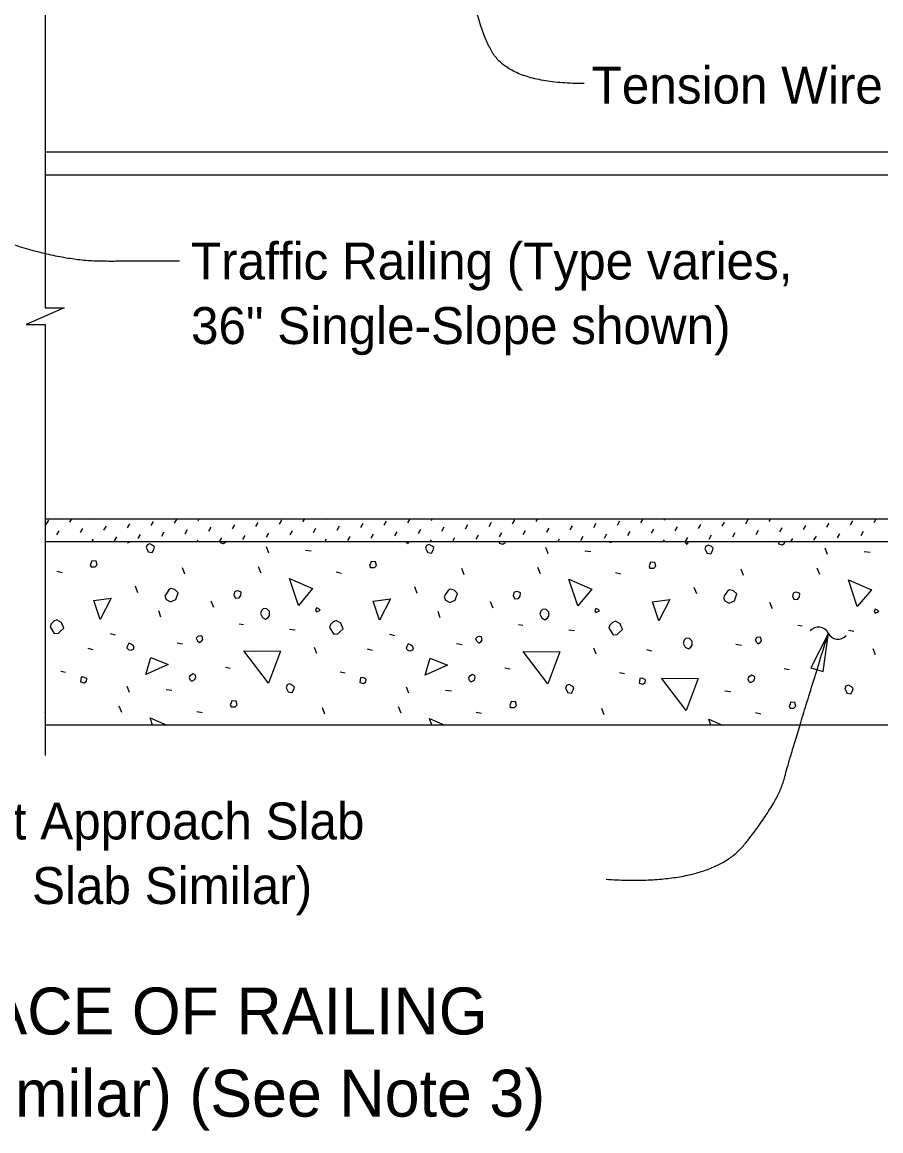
# Model space of a CAD drawing. Extents: x 0 to 72.1, y -15.2 to 30.1.
# Drawn here: x 16.14 to 20.83, y 12.94 to 18.99 of the extents above; entities that cross this region are included whole.
import ezdxf

# ---------------------------------------------------------------- set-up
doc = ezdxf.new("R2010")
doc.units = 0
for name, color, linetype in [('AdhocPoint_dp', 7, 'Continuous'), ('Patterning', 7, 'Continuous'), ('PlotBorder_dp', 7, 'Continuous'), ('SheetLines_dp', 7, 'Continuous')]:
    doc.layers.add(name, color=color, linetype=linetype)

msp = doc.modelspace()

# ---------------------------------------------------------------- linework, layer by layer
at = {"layer": 'AdhocPoint_dp'}
for p, q in [((16.268, 18.2783), (23.5698, 18.2783)), ((16.268, 18.1533), (23.5699, 18.1533)), ((16.268, 16.2783), (23.5698, 16.2783)), ((21.5698, 16.1533), (16.268, 16.1533)), ((21.9525, 15.1533), (16.268, 15.1533))]:
    msp.add_line(p, q, dxfattribs=at)
at = {"layer": 'Patterning'}
for p, q in [((16.2748, 16.2476), (16.2877, 16.27)), ((16.4032, 16.2606), (16.4135, 16.2783)), ((16.5317, 16.2735), (16.5344, 16.2783)), ((16.8463, 16.2417), (16.8593, 16.2641)), ((16.9748, 16.2547), (16.9878, 16.2771)), ((17.1032, 16.2677), (17.1094, 16.2783)), ((17.5464, 16.2488), (17.5593, 16.2712)), ((17.6748, 16.2618), (17.6844, 16.2783)), ((17.8033, 16.2747), (17.8054, 16.2783)), ((18.1179, 16.2429), (18.1309, 16.2653)), ((18.2464, 16.2559), (18.2594, 16.2783)), ((18.3749, 16.2688), (18.3803, 16.2783)), ((18.818, 16.25), (18.8309, 16.2724)), ((18.9464, 16.2629), (18.9553, 16.2783)), ((19.0749, 16.2759), (19.0763, 16.2783)), ((19.3896, 16.2441), (19.4025, 16.2665)), ((19.518, 16.257), (19.5303, 16.2783)), ((19.6465, 16.27), (19.6513, 16.2783)), ((19.9611, 16.2382), (19.9741, 16.2606)), ((20.0896, 16.2512), (20.1026, 16.2735)), ((20.2181, 16.2641), (20.2263, 16.2783)), ((20.3465, 16.2771), (20.3472, 16.2783)), ((20.6612, 16.2453), (20.6741, 16.2677)), ((20.7896, 16.2582), (20.8013, 16.2783)), ((16.3325, 16.1899), (16.3455, 16.2123)), ((16.461, 16.2028), (16.4739, 16.2252)), ((16.5894, 16.2158), (16.6024, 16.2382)), ((16.7179, 16.2288), (16.7308, 16.2512)), ((16.9041, 16.184), (16.917, 16.2064)), ((17.0325, 16.1969), (17.0455, 16.2193)), ((17.161, 16.2099), (17.174, 16.2323)), ((17.2895, 16.2229), (17.3024, 16.2453)), ((17.4179, 16.2358), (17.4309, 16.2582)), ((17.4757, 16.1781), (17.4886, 16.2005)), ((17.6041, 16.191), (17.6171, 16.2134)), ((17.7326, 16.204), (17.7455, 16.2264)), ((17.861, 16.217), (17.874, 16.2394)), ((17.9895, 16.2299), (18.0024, 16.2523)), ((18.1757, 16.1852), (18.1887, 16.2075)), ((18.3041, 16.1981), (18.3171, 16.2205)), ((18.4326, 16.2111), (18.4456, 16.2335)), ((18.5611, 16.224), (18.574, 16.2464)), ((18.6895, 16.237), (18.7025, 16.2594)), ((18.7473, 16.1793), (18.7602, 16.2017)), ((18.8757, 16.1922), (18.8887, 16.2146)), ((19.0042, 16.2052), (19.0171, 16.2276)), ((19.1326, 16.2182), (19.1456, 16.2405)), ((19.2611, 16.2311), (19.2741, 16.2535)), ((19.4473, 16.1863), (19.4603, 16.2087)), ((19.5758, 16.1993), (19.5887, 16.2217)), ((19.7042, 16.2123), (19.7172, 16.2347)), ((19.8327, 16.2252), (19.8456, 16.2476)), ((20.0189, 16.1804), (20.0318, 16.2028)), ((20.1473, 16.1934), (20.1603, 16.2158)), ((20.2758, 16.2064), (20.2888, 16.2288)), ((20.4043, 16.2193), (20.4172, 16.2417)), ((20.5327, 16.2323), (20.5457, 16.2547)), ((20.7189, 16.1875), (20.7319, 16.2099)), ((16.5235, 16.1533), (16.5317, 16.1675)), ((16.6472, 16.1581), (16.6601, 16.1804)), ((16.7756, 16.171), (16.7886, 16.1934)), ((17.0985, 16.1533), (17.1032, 16.1616)), ((17.2194, 16.1533), (17.2317, 16.1746)), ((17.3472, 16.1651), (17.3602, 16.1875)), ((17.6735, 16.1533), (17.6748, 16.1557)), ((17.7944, 16.1533), (17.8033, 16.1687)), ((17.9188, 16.1592), (17.9317, 16.1816)), ((18.0472, 16.1722), (18.0602, 16.1946)), ((18.3694, 16.1533), (18.3749, 16.1628)), ((18.4904, 16.1533), (18.5033, 16.1757)), ((18.6188, 16.1663), (18.6318, 16.1887)), ((19.0653, 16.1533), (19.0749, 16.1698)), ((19.1904, 16.1604), (19.2034, 16.1828)), ((19.3188, 16.1734), (19.3318, 16.1958)), ((19.6403, 16.1533), (19.6465, 16.1639)), ((19.762, 16.1545), (19.7749, 16.1769)), ((19.8904, 16.1675), (19.9034, 16.1899)), ((20.2153, 16.1533), (20.2181, 16.1581)), ((20.3363, 16.1533), (20.3465, 16.171)), ((20.462, 16.1616), (20.475, 16.184)), ((20.5905, 16.1746), (20.6034, 16.1969)), ((17.4887, 16.0909), (17.4763, 16.1245)), ((17.6885, 16.1068), (17.7203, 16.1033)), ((19.0125, 16.0874), (19.0002, 16.121)), ((19.2123, 16.1033), (19.2441, 16.0998)), ((20.5363, 16.0839), (20.524, 16.1174)), ((20.7361, 16.0998), (20.7679, 16.0962)), ((16.3326, 15.9919), (16.3609, 15.9849)), ((17.0309, 15.976), (17.0167, 16.0114)), ((17.4463, 15.9813), (17.4321, 16.0167)), ((17.8564, 15.9884), (17.8847, 15.9813)), ((18.5547, 15.9725), (18.5405, 16.0078)), ((18.9701, 15.9778), (18.956, 16.0131)), ((19.3802, 15.9849), (19.4085, 15.9778)), ((20.0785, 15.969), (20.0644, 16.0043)), ((20.4939, 15.9743), (20.4798, 16.0096)), ((16.7745, 15.8753), (16.7604, 15.9106)), ((18.2984, 15.8717), (18.2842, 15.9071)), ((19.8222, 15.8682), (19.808, 15.9035)), ((16.9, 15.7427), (16.8877, 15.7763)), ((17.1882, 15.7939), (17.1741, 15.8293)), ((18.712, 15.7904), (18.6979, 15.8258)), ((20.2358, 15.7869), (20.2217, 15.8222)), ((18.4239, 15.7391), (18.4115, 15.7727)), ((17.3261, 15.7056), (17.3508, 15.702)), ((17.6019, 15.6773), (17.6319, 15.672)), ((18.8499, 15.702), (18.8746, 15.6985)), ((19.1257, 15.6737), (19.1557, 15.6684)), ((20.3737, 15.6985), (20.3985, 15.6949)), ((20.6495, 15.6702), (20.6795, 15.6649)), ((16.6225, 15.6525), (16.6508, 15.6455)), ((16.9884, 15.6013), (17.0185, 15.596)), ((18.1463, 15.649), (18.1746, 15.6419)), ((18.5123, 15.5977), (18.5423, 15.5924)), ((16.5005, 15.573), (16.5288, 15.5659)), ((17.7503, 15.5429), (17.738, 15.5765)), ((18.0243, 15.5694), (18.0526, 15.5624)), ((19.2742, 15.5394), (19.2618, 15.573)), ((19.5482, 15.5659), (19.5764, 15.5588)), ((20.0361, 15.5942), (20.0661, 15.5889)), ((20.798, 15.5359), (20.7856, 15.5694)), ((16.3538, 15.4475), (16.3803, 15.4422)), ((17.2518, 15.4687), (17.2784, 15.4634)), ((17.8776, 15.4439), (17.9041, 15.4386)), ((18.7757, 15.4651), (18.8022, 15.4598)), ((19.4014, 15.4404), (19.428, 15.4351)), ((20.2995, 15.4616), (20.326, 15.4563)), ((16.7286, 15.3308), (16.7162, 15.3644)), ((18.2524, 15.3273), (18.24, 15.3608)), ((16.9283, 15.3467), (16.9602, 15.3432)), ((18.4521, 15.3432), (18.484, 15.3396)), ((19.976, 15.3396), (20.0078, 15.3361)), ((16.6861, 15.2212), (16.672, 15.2565)), ((17.7945, 15.2123), (17.7804, 15.2477)), ((18.21, 15.2177), (18.1958, 15.253)), ((19.3184, 15.2088), (19.3042, 15.2442)), ((16.2707, 15.2159), (16.268, 15.2227)), ((17.0963, 15.2283), (17.1246, 15.2212)), ((18.6201, 15.2247), (18.6484, 15.2177)), ((20.1439, 15.2212), (20.1722, 15.2141))]:
    msp.add_line(p, q, dxfattribs=at)
for points in [[(16.7233, 16.1457), (16.7175, 16.1533)], [(16.7261, 16.1533), (16.7233, 16.1457)], [(16.8223, 16.1139), (16.8311, 16.098), (16.8523, 16.0945), (16.8612, 16.1104), (16.8647, 16.1245), (16.8559, 16.1334), (16.8399, 16.1422), (16.824, 16.1369), (16.8187, 16.121), (16.8223, 16.1139)], [(17.2218, 16.1493), (17.2412, 16.144), (17.2536, 16.1528), (17.2537, 16.1533)], [(17.2224, 16.1533), (17.2218, 16.1493)], [(18.2471, 16.1422), (18.2386, 16.1533)], [(18.2513, 16.1533), (18.2471, 16.1422)], [(18.3461, 16.1104), (18.3549, 16.0945), (18.3761, 16.0909), (18.385, 16.1068), (18.3885, 16.121), (18.3797, 16.1298), (18.3638, 16.1387), (18.3479, 16.1334), (18.3425, 16.1174), (18.3461, 16.1104)], [(18.7456, 16.1457), (18.765, 16.1404), (18.7774, 16.1493), (18.778, 16.1533)], [(18.7467, 16.1533), (18.7456, 16.1457)], [(19.3461, 16.1533), (19.3484, 16.151)], [(19.3484, 16.151), (19.3555, 16.151), (19.3601, 16.1533)], [(19.7709, 16.1387), (19.7597, 16.1533)], [(19.7764, 16.1533), (19.7709, 16.1387)], [(20.2694, 16.1422), (20.2889, 16.1369), (20.3012, 16.1457), (20.3023, 16.1533)], [(20.271, 16.1533), (20.2694, 16.1422)], [(19.8699, 16.1068), (19.8787, 16.0909), (19.9, 16.0874), (19.9088, 16.1033), (19.9123, 16.1174), (19.9035, 16.1263), (19.8876, 16.1351), (19.8717, 16.1298), (19.8664, 16.1139), (19.8699, 16.1068)], [(16.52, 16.0167), (16.5412, 16.0167), (16.5518, 16.0273), (16.5465, 16.0467), (16.5235, 16.0485), (16.52, 16.0379), (16.5147, 16.0291), (16.52, 16.0167), (16.5164, 16.0202)], [(18.0438, 16.0131), (18.065, 16.0131), (18.0756, 16.0238), (18.0703, 16.0432), (18.0473, 16.045), (18.0438, 16.0344), (18.0385, 16.0255), (18.0438, 16.0131), (18.0403, 16.0167)], [(19.5676, 16.0096), (19.5888, 16.0096), (19.5994, 16.0202), (19.5941, 16.0397), (19.5711, 16.0414), (19.5676, 16.0308), (19.5623, 16.022), (19.5676, 16.0096), (19.5641, 16.0131)], [(16.9283, 15.8381), (16.9513, 15.8258), (16.9814, 15.8381), (16.9937, 15.8753), (16.9761, 15.8929), (16.9531, 15.8982), (16.9425, 15.8912), (16.9301, 15.8717), (16.9213, 15.8558), (16.9283, 15.8381)], [(17.6496, 15.8063), (17.6019, 15.953), (17.7274, 15.8982), (17.6496, 15.8063)], [(19.1734, 15.8028), (19.1257, 15.9495), (19.2512, 15.8947), (19.1734, 15.8028)], [(20.6972, 15.7992), (20.6495, 15.946), (20.775, 15.8912), (20.6972, 15.7992)], [(16.5677, 15.7285), (16.5341, 15.8328), (16.6278, 15.8452), (16.5677, 15.7285)], [(17.2978, 15.8611), (17.3066, 15.8452), (17.3261, 15.847), (17.3349, 15.8594), (17.3367, 15.8788), (17.3243, 15.8841), (17.3155, 15.8859), (17.3049, 15.8823), (17.3013, 15.8788), (17.2978, 15.8611)], [(18.0915, 15.725), (18.0579, 15.8293), (18.1516, 15.8417), (18.0915, 15.725)], [(18.4521, 15.8346), (18.4751, 15.8222), (18.5052, 15.8346), (18.5176, 15.8717), (18.4999, 15.8894), (18.4769, 15.8947), (18.4663, 15.8876), (18.4539, 15.8682), (18.4451, 15.8523), (18.4521, 15.8346)], [(18.8216, 15.8576), (18.8305, 15.8417), (18.8499, 15.8434), (18.8587, 15.8558), (18.8605, 15.8753), (18.8481, 15.8806), (18.8393, 15.8823), (18.8287, 15.8788), (18.8251, 15.8753), (18.8216, 15.8576)], [(19.6153, 15.7215), (19.5818, 15.8258), (19.6754, 15.8381), (19.6153, 15.7215)], [(19.976, 15.8311), (19.9989, 15.8187), (20.029, 15.8311), (20.0414, 15.8682), (20.0237, 15.8859), (20.0007, 15.8912), (19.9901, 15.8841), (19.9777, 15.8647), (19.9689, 15.8487), (19.976, 15.8311)], [(20.3454, 15.854), (20.3543, 15.8381), (20.3737, 15.8399), (20.3826, 15.8523), (20.3843, 15.8717), (20.3719, 15.877), (20.3631, 15.8788), (20.3525, 15.8753), (20.349, 15.8717), (20.3454, 15.854)], [(17.4428, 15.7621), (17.4534, 15.7409), (17.471, 15.7303), (17.4852, 15.7409), (17.4923, 15.7515), (17.4923, 15.7727), (17.4763, 15.7886), (17.4569, 15.7869), (17.4481, 15.778), (17.4428, 15.7621)], [(17.7486, 15.771), (17.768, 15.7798), (17.761, 15.7869), (17.7486, 15.7922), (17.7433, 15.7798), (17.7486, 15.771)], [(18.9666, 15.7586), (18.9772, 15.7374), (18.9949, 15.7268), (19.009, 15.7374), (19.0161, 15.748), (19.0161, 15.7692), (19.0002, 15.7851), (18.9807, 15.7833), (18.9719, 15.7745), (18.9666, 15.7586)], [(19.2724, 15.7674), (19.2918, 15.7763), (19.2848, 15.7833), (19.2724, 15.7886), (19.2671, 15.7763), (19.2724, 15.7674)], [(20.7962, 15.7639), (20.8157, 15.7727), (20.8086, 15.7798), (20.7962, 15.7851), (20.7909, 15.7727), (20.7962, 15.7639)], [(16.2955, 15.6896), (16.3185, 15.6525), (16.3414, 15.6543), (16.3503, 15.6631), (16.3697, 15.6826), (16.3573, 15.7126), (16.3326, 15.7268), (16.3149, 15.7197), (16.3008, 15.7056), (16.2955, 15.6896)], [(17.8193, 15.6861), (17.8423, 15.649), (17.8653, 15.6508), (17.8741, 15.6596), (17.8935, 15.679), (17.8812, 15.7091), (17.8564, 15.7232), (17.8387, 15.7162), (17.8246, 15.702), (17.8193, 15.6861)], [(19.3431, 15.6826), (19.3661, 15.6455), (19.3891, 15.6472), (19.3979, 15.6561), (19.4173, 15.6755), (19.405, 15.7056), (19.3802, 15.7197), (19.3625, 15.7126), (19.3484, 15.6985), (19.3431, 15.6826)], [(16.725, 15.5641), (16.7374, 15.5624), (16.7498, 15.5677), (16.7533, 15.5783), (16.748, 15.5871), (16.7374, 15.5942), (16.725, 15.5995), (16.718, 15.5853), (16.7144, 15.5747), (16.725, 15.5641)], [(17.0998, 15.6136), (17.1104, 15.603), (17.121, 15.6101), (17.1281, 15.6207), (17.1246, 15.6384), (17.1157, 15.6401), (17.1033, 15.6384), (17.0927, 15.6278), (17.0998, 15.6136)], [(18.2489, 15.5606), (18.2612, 15.5588), (18.2736, 15.5641), (18.2771, 15.5747), (18.2718, 15.5836), (18.2612, 15.5907), (18.2489, 15.596), (18.2418, 15.5818), (18.2382, 15.5712), (18.2489, 15.5606)], [(18.6236, 15.6101), (18.6342, 15.5995), (18.6448, 15.6066), (18.6519, 15.6172), (18.6484, 15.6348), (18.6395, 15.6366), (18.6272, 15.6348), (18.6166, 15.6242), (18.6236, 15.6101)], [(19.7485, 15.6004), (19.7591, 15.5792), (19.7768, 15.5686), (19.791, 15.5792), (19.798, 15.5898), (19.798, 15.611), (19.7821, 15.6269), (19.7627, 15.6252), (19.7538, 15.6163), (19.7485, 15.6004)], [(20.1474, 15.6066), (20.158, 15.596), (20.1687, 15.603), (20.1757, 15.6136), (20.1722, 15.6313), (20.1633, 15.6331), (20.151, 15.6313), (20.1404, 15.6207), (20.1474, 15.6066)], [(17.4869, 15.3821), (17.3526, 15.5588), (17.5524, 15.5571), (17.4869, 15.3821)], [(19.0108, 15.3785), (18.8764, 15.5553), (19.0762, 15.5535), (19.0108, 15.3785)], [(16.817, 15.4298), (16.8452, 15.5217), (16.9389, 15.4846), (16.817, 15.4298)], [(18.3408, 15.4262), (18.3691, 15.5182), (18.4628, 15.481), (18.3408, 15.4262)], [(16.4616, 15.3891), (16.4811, 15.3838), (16.4935, 15.3927), (16.4952, 15.405), (16.4917, 15.4086), (16.4776, 15.4156), (16.4652, 15.4139), (16.4634, 15.4015), (16.4616, 15.3891)], [(17.0645, 15.3944), (17.0715, 15.3944), (17.0857, 15.4015), (17.091, 15.4174), (17.0892, 15.4262), (17.0751, 15.4333), (17.0574, 15.4227), (17.0538, 15.4121), (17.0574, 15.4015), (17.0645, 15.3944)], [(18.5883, 15.3909), (18.5953, 15.3909), (18.6095, 15.398), (18.6148, 15.4139), (18.613, 15.4227), (18.5989, 15.4298), (18.5812, 15.4192), (18.5777, 15.4086), (18.5812, 15.398), (18.5883, 15.3909)], [(20.1121, 15.3874), (20.1192, 15.3874), (20.1333, 15.3944), (20.1386, 15.4103), (20.1368, 15.4192), (20.1227, 15.4262), (20.105, 15.4156), (20.1015, 15.405), (20.105, 15.3944), (20.1121, 15.3874)], [(17.5859, 15.3502), (17.5948, 15.3343), (17.616, 15.3308), (17.6248, 15.3467), (17.6284, 15.3608), (17.6195, 15.3697), (17.6036, 15.3785), (17.5877, 15.3732), (17.5824, 15.3573), (17.5859, 15.3502)], [(17.9855, 15.3856), (18.0049, 15.3803), (18.0173, 15.3891), (18.019, 15.4015), (18.0155, 15.405), (18.0014, 15.4121), (17.989, 15.4103), (17.9872, 15.398), (17.9855, 15.3856)], [(19.1098, 15.3467), (19.1186, 15.3308), (19.1398, 15.3273), (19.1486, 15.3432), (19.1522, 15.3573), (19.1433, 15.3661), (19.1274, 15.375), (19.1115, 15.3697), (19.1062, 15.3538), (19.1098, 15.3467)], [(19.5093, 15.3821), (19.5287, 15.3768), (19.5411, 15.3856), (19.5429, 15.398), (19.5393, 15.4015), (19.5252, 15.4086), (19.5128, 15.4068), (19.511, 15.3944), (19.5093, 15.3821)], [(19.7646, 15.2332), (19.6303, 15.41), (19.83, 15.4082), (19.7646, 15.2332)], [(20.6336, 15.3432), (20.6424, 15.3273), (20.6636, 15.3237), (20.6725, 15.3396), (20.676, 15.3538), (20.6672, 15.3626), (20.6513, 15.3714), (20.6353, 15.3661), (20.63, 15.3502), (20.6336, 15.3432)], [(17.2837, 15.253), (17.3049, 15.253), (17.3155, 15.2636), (17.3102, 15.2831), (17.2872, 15.2848), (17.2837, 15.2742), (17.2784, 15.2654), (17.2837, 15.253), (17.2801, 15.2565)], [(18.8075, 15.2495), (18.8287, 15.2495), (18.8393, 15.2601), (18.834, 15.2795), (18.811, 15.2813), (18.8075, 15.2707), (18.8022, 15.2618), (18.8075, 15.2495), (18.8039, 15.253)], [(20.3313, 15.2459), (20.3525, 15.2459), (20.3631, 15.2565), (20.3578, 15.276), (20.3348, 15.2778), (20.3313, 15.2671), (20.326, 15.2583), (20.3313, 15.2459), (20.3277, 15.2495)], [(16.8546, 15.1533), (16.8417, 15.1929), (16.9324, 15.1533)], [(18.3773, 15.1533), (18.3655, 15.1894), (18.4481, 15.1533)], [(19.8999, 15.1533), (19.8893, 15.1858), (19.9638, 15.1533)]]:
    msp.add_lwpolyline(points, dxfattribs=at)
at = {"layer": 'PlotBorder_dp'}
msp.add_lwpolyline([(16.268, 19.2784), (16.268, 17.4276), (16.3714, 17.4276), (16.268, 17.3826), (16.1647, 17.3376), (16.268, 17.3376), (16.268, 14.9877)], dxfattribs=at)
msp.add_lwpolyline([(20.5406, 15.6543), (20.4449, 15.466), (20.5122, 15.445)], close=True, dxfattribs=at)
for centre, start, end in [((20.4866, 15.6275), 26.84133, 138.56855), ((20.593, 15.6813), 206.84133, 318.56855)]:
    msp.add_arc(centre, 0.0596, start, end, dxfattribs=at)
for points in [[(19.2088, 18.651), (18.8109, 18.651), (18.6069, 18.988), (18.5457, 19.4449)], [(17.0013, 17.682), (16.9314, 17.682), (16.232, 17.682), (15.6743, 17.939)], [(19.3291, 14.3127), (19.9021, 14.2762), (20.2669, 14.7328), (20.3333, 14.9902), (20.5406, 15.6542)]]:
    msp.add_open_spline(points, degree=2, dxfattribs=at)

# ---------------------------------------------------------------- texts
for s, height, p in [('Traffic Railing (Type varies,', 0.2016, (17.0639, 17.5829)), ('36" Single-Slope shown)', 0.2016, (17.0639, 17.2309)), ('Approach Slab (Flexible Pavement Approach Slab ', 0.2016, (12.0159, 14.5298)), ('Shown, Rigid Pavement Approach Slab Similar)', 0.2016, (12.0159, 14.1778)), ('ELEVATION OF OUTSIDE FACE OF RAILING', 0.256001, (11.5294, 13.4666)), ('(Traffic Railing Shown, Concrete Parapet Similar) (See Note 3)', 0.256001, (9.4828, 13.0186))]:
    msp.add_text(s, height=height, dxfattribs=at).set_placement(p)
at = {"layer": 'SheetLines_dp'}
msp.add_text('Tension Wire', height=0.2016, dxfattribs=at).set_placement((19.2495, 18.5415))

doc.saveas('drawing.dxf')
